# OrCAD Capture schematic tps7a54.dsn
size A
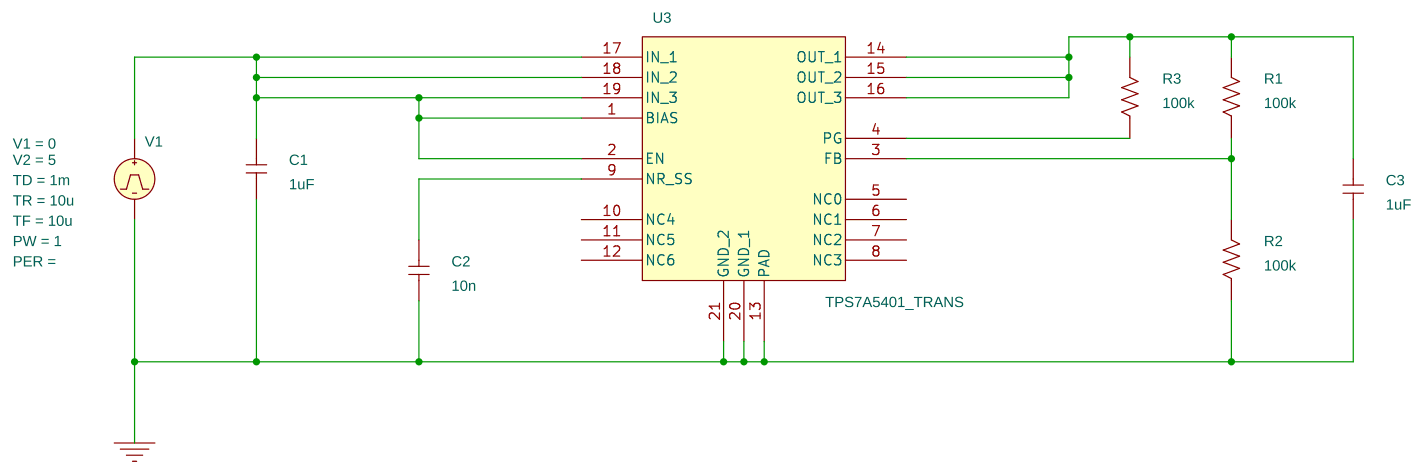
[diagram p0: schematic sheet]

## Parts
C1  1uF  [cap196]
C2  10n  [cap196]
C3  1uF  [cap196]
R1  100k  [AXRC05]
R2  100k  [AXRC05]
R3  100k  [AXRC05]
U3  TPS7A5401_TRANS
V1  VPULSE

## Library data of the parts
C1-C3 = C
R1-R3 = R
U3 = TPS7A5401_TRANS_1
V1 = VPULSE: PW: 1; TD: 1m; TF: 10u; TR: 10u; V1: 0; V2: 5

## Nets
0: C1.1 C2.1 C3.1 R2.1 U3.13(PAD) U3.20(GND_1) U3.21(GND_2) V1.2(-)
N00381: C1.2 U3.1(BIAS) U3.2(EN) U3.17(IN_1) U3.18(IN_2) U3.19(IN_3) V1.1(+)
N00720: C2.2 U3.9(NR_SS)
N00772: C3.2 R1.2 R3.2 U3.14(OUT_1) U3.15(OUT_2) U3.16(OUT_3)
N00920: R1.1 R2.2 U3.3(FB)
N01401: R3.1 U3.4(PG)

Not connected (* = marked no-connect by the designer): U3 5(NC0) 6(NC1) 7(NC2) 8(NC3) 10(NC4) 11(NC5) 12(NC6)
